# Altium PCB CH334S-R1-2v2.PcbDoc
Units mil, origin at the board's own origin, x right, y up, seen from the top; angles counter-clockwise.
Board outline 3110.24 x 866.14 mil, 2 copper layers (Top Layer, Bottom Layer); 18 components, 20 nets, 106 pads, 265 vias.
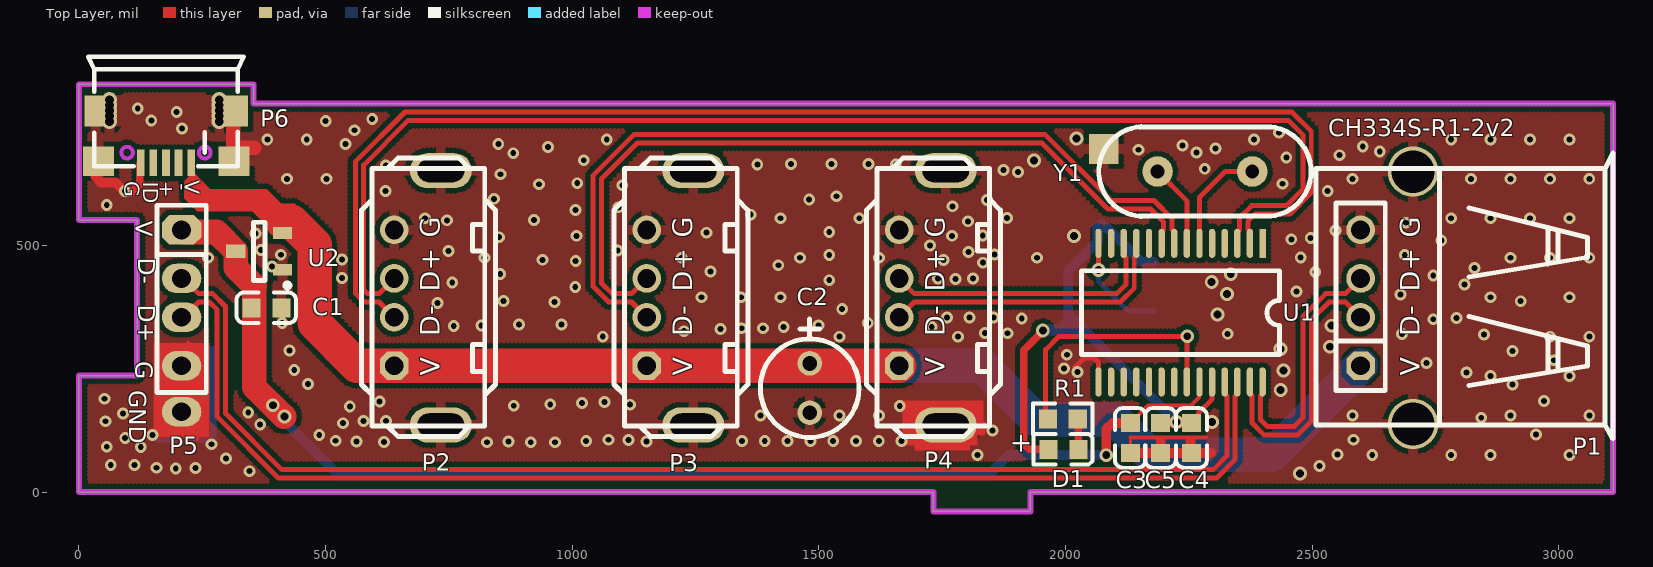
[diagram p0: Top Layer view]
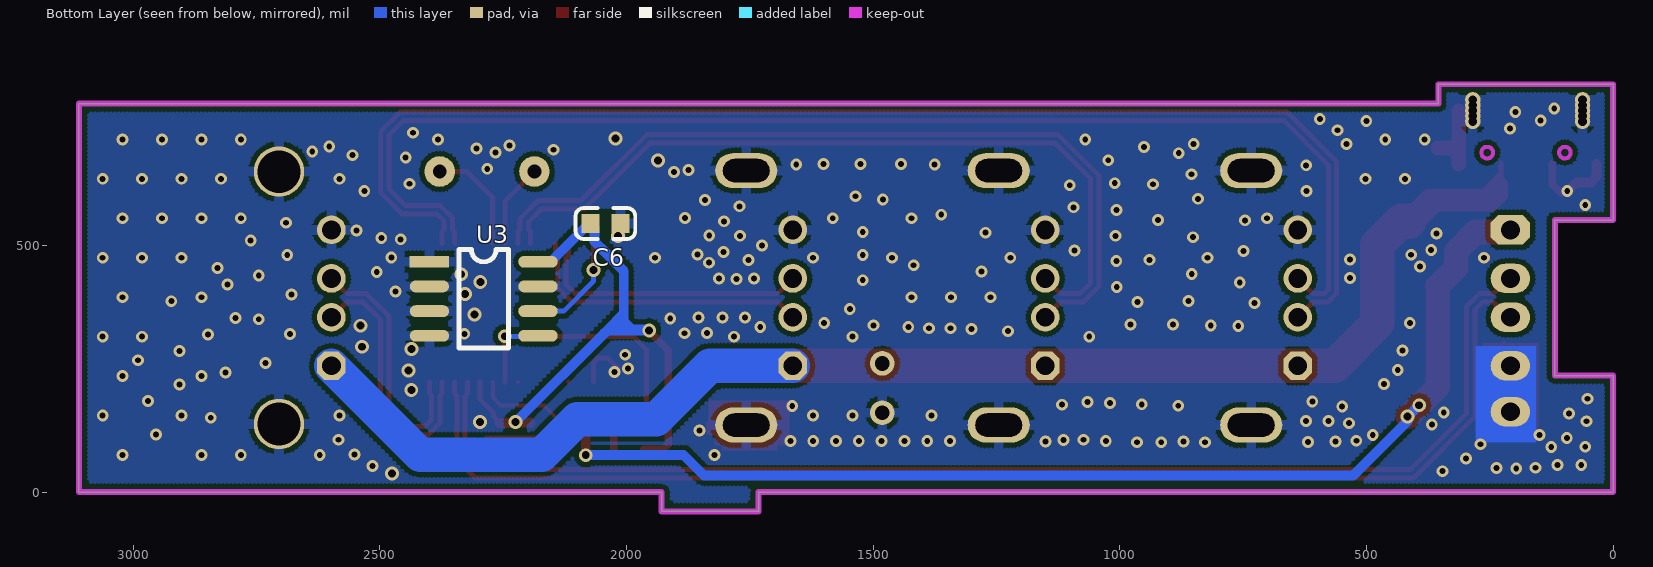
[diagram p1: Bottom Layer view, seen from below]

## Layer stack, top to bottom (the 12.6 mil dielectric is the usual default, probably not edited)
Top Solder: solder mask 0.4, Solder Resist, Dk 3.5
Top Layer: signal copper 1.4
Dielectric 1: dielectric 12.6, FR-4, Dk 4.8
Bottom Layer: signal copper 1.4
Bottom Solder: solder mask 0.4, Solder Resist, Dk 3.5

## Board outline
0,0 0,236.22 118.11,236.22 118.11,551.18 0,551.18 0,826.77 354.33,826.77 354.33,787.4 3110.24,787.4 3110.24,0 1929.13,0 1929.13,-39.37 1732.28,-39.37 1732.28,0

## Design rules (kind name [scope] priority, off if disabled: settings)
Clearance Clearance_1 [InPolygon] p1: gap=10 ignorepadtopadclearanceinfootprint=FALSE
Clearance [All] p2: gap=6 ignorepadtopadclearanceinfootprint=FALSE except(8: Arc-Via Track-Via SMDPad-Via THPad-Via Via-Via Via-Fill Via-Poly Via-Region Via-Hole)
ComponentClearance [All] p1 off: gap=10 collisioncheckmode=3 verticalgap=10 showdistances=FALSE
DiffPairsRouting [All] p1: maxlimit=10 minlimit=7 mostfreqgap=8 toplayer_minwidth=6 toplayer_maxwidth=15 toplayer_prefwidth=8 bottomlayer_minwidth=6 bottomlayer_maxwidth=15 bottomlayer_prefwidth=8 maxuncoupledlength=500
MinimumSolderMaskSliver [All] p1 off: minsoldermaskwidth=10
PolygonConnect PolygonConnect_1 [IsVia] p1: connectstyle=Direct reliefconductorwidth=10 reliefentries=4 polygonreliefangle="90 Angle" airgapwidth=10
PolygonConnect [All] p2: connectstyle=Relief reliefconductorwidth=20 reliefentries=4 polygonreliefangle="90 Angle" airgapwidth=10
RoutingVias [All] p1: holewidth=16 width=28 viastyle="Through Hole" minholewidth=12 minwidth=24 maxholewidth=28 maxwidth=50
SilkToSilkClearance [All] p1 off: silktosilkclearance=10
SilkToSolderMaskClearance [IsPad] p1 off: minsilkscreentomaskgap=10 clearancetoexposedcopper=TRUE
SolderMaskExpansion [All] p1: expansion=4 istentingtop=FALSE
Width [All] p1: maxlimit=100 minlimit=6 preferedwidth=10
25 further rules are at their usual default settings.

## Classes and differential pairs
differential pair UD: +UD_p -UD_n
differential pair UD4: +UD4_p -UD4_n
differential pair UD3: +UD3_p -UD3_n
differential pair UD2: +UD2_p -UD2_n
differential pair UD1: +UD1_p -UD1_n

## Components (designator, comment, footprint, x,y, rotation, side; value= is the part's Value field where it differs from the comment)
C1 "10uF" 0603_C 349.72,373.57 r0 top
C2 "220uF" CD0.1 1481.53,260.82 r270 top
C3 "1uF" 0603_C 2131.41,140.12 r270 top
C4 "0.1uF" 0603_C 2255.54,140.12 r270 top
C5 "10uF" 0603_C 2192.47,140.12 r270 top
C6 "NC(1uF)" 0603_C 2012.47,544.44 r0 bottom
D1 "LED" 0603+ 1965.61,86.66 r0 top
P1 "USB" USBAF#1 2598.25,255.91 r90 top
P2 "USB" USB2.0-A-F-TH_4P-V_13.7mm 639.21,255.91 r180 top
P3 "USB" USB2.0-A-F-TH_4P-V_13.7mm 1151.02,255.91 r180 top
P4 "USB" USB2.0-A-F-TH_4P-V_13.7mm 1662.83,255.91 r180 top
P5 "USB" USBAF#2 208.21,531.5 r270 top
P6 "Power Supply" USBMICROB-02-GXPX-A1T2 227.66,667.45 r180 top
R1 "1K" 0603_R 1994.55,148.31 r0 top
U1 "CH334S" SSOP28 2399.61,504.17 r180 top
U2 "CH213K" SOT-23-3 412.79,450.5 r90 top
U3 "NC(24C02)" SOIC-8_150mil 2399.58,466.78 r270 bottom
Y1 "12M" XT_AT49 2186.69,649.86 r270 top

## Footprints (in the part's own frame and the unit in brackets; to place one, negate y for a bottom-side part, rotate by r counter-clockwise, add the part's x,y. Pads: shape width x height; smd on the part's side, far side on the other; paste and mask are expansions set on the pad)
0603+ [mm]
  rect 0.93x0.98 smd: 1(0,0) 2(1.54,0)
  silkscreen extent -0.76,-0.79 2.27,0.79
0603_C [mm]
  rect 0.93x0.98 smd: 1(0,0) 2(1.54,0)
  silkscreen extent -0.76,-0.79 2.31,0.79
0603_R [mm]
  rect 0.93x0.98 smd: 1(-0.77,0) 2(0.77,0)
  silkscreen extent -1.53,-0.79 1.54,0.79
CD0.1 [mil]
  round 50 hole 30: 1(0,0) 2(100,0)
  silkscreen extent -90,-100 150,100
SOIC-8_150mil [mil]
  rect 24x80 smd: 1(0,0)
  oval 24x80 smd: 2(50,0) 3(100,0) 4(150,0) 5(150,220) 6(100,220) 7(50,220) 8(0,220)
  silkscreen extent -25,60 175,160
SOT-23-3 [mm] "SOT-23-3"
  rect 0.6x1 smd: 1(0,0) 2(1.9,0)
  rect 0.7x1 smd: 3(0.95,2.4)
  silkscreen extent -0.93,-0.38 2.45,1.49
SSOP28 [mil]
  rect 13x59.06 smd: 1(0,0)
  oval 13x59.06 smd: 2(25.59,0) 3(51.18,0) 4(76.77,0) 5(102.36,0) 6(127.95,0) 7(153.55,0) 8(179.14,0) 9(204.73,0) 10(230.32,0) 11(255.91,0) 12(281.5,0) 13(307.09,0) 14(332.68,0) 15(332.68,280.94) 16(307.09,280.94) 17(281.5,280.94) 18(255.91,280.94) 19(230.32,280.94) 20(204.73,280.94) 21(179.14,280.94) 22(153.55,280.94) 23(127.95,280.94) 24(102.36,280.94) 25(76.77,280.94) 26(51.18,280.94) 27(25.59,280.94) 28(0,280.94)
  silkscreen extent -34,55 367,225
USB2.0-A-F-TH_4P-V_13.7mm [mm]
  oval 3.2x1.8 hole 1.2 slot 2.4 at 0 deg: 0(-2.4,3.05) 0(-2.4,-10.05)
  oct 1.473x1.473 hole 0.965: 1(0,0)
  round 1.473 hole 0.965: 2(0,-2.5) 3(0,-4.5) 4(0,-7)
  silkscreen extent -5.21,-10.71 1.69,3.65
USBAF#1 [mm]
  round 2.6 hole 2.2: 0(-3,-2.7) 0(10,-2.7)
  oct 1.473x1.473 hole 0.965: 1(0,0)
  round 1.473 hole 0.965: 2(2.5,0) 3(4.5,0) 4(7,0)
  silkscreen extent -3.75,-12.99 10.95,2.29
USBAF#2 [mm]
  oct 1.524x2.032 hole 0.965: 1(0,0)
  oval 1.524x2.032 hole 0.965: 2(2.5,0) 3(4.5,0) 4(7,0)
  silkscreen extent -1.27,-1.27 8.38,1.27
USBMICROB-02-GXPX-A1T2 [mm]
  rect 1.6x1.5 smd: 0(-2.203,-0.083) 0(4.769,-0.083)
  rect 1.5x1.6 smd: 0(-2.167,-2.675)
  round 0.8 hole 0.45: 0(-1.442,-2.134) 0(-1.442,-3.243) 0(-1.442,-2.966) 0(-1.442,-2.689) 0(-1.442,-2.411) 0(4.208,-2.689) 0(4.208,-2.411) 0(4.208,-2.134) 0(4.208,-3.243) 0(4.208,-2.966)
  rect 1.1x1.6 smd: 0(4.933,-2.675)
  rect 0.4x1.35 smd mask+0.051: 1(0,0) 2(0.65,0) 3(1.3,0) 4(1.95,0) 5(2.6,0)
  Keep-Out Layer circle w0.203: c3.3,-0.525 r0.3
  Keep-Out Layer circle w0.203: c-0.7,-0.525 r0.3
  silkscreen extent -2.7,-5.46 5.3,0.17
XT_AT49 [mil]
  rect 60x60 smd: 0(-45.58,-109.21)
  round 62 hole 28: 1(0,0) 2(0,192.13)
  silkscreen extent -91,-119 91,311

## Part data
C1 C2 C3 C4 C5 C6: library part CAP, "Capacitor"
D1: "Typical INFRARED GaAs LED"
P1 P2 P3 P4 P5: "USB Port"
P6: library part MicroUSB, "MicroUSB Port"
R1: library part RES
U1: "4 ports High-Speed USB MTT Hub with over current detect & power control"
U2: "Ideal Diode 5V*1A"
U3: library part 24C01
Y1: library part XTAL, "Crystal Oscillator"

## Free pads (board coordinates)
  oval 80x60 hole 38: ""(208.21,162.81)

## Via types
v1: diameter 24, hole 12, Top Layer to Bottom Layer, tented both sides, 244 vias
v2: diameter 28, hole 16, Top Layer to Bottom Layer, tented both sides, 21 vias

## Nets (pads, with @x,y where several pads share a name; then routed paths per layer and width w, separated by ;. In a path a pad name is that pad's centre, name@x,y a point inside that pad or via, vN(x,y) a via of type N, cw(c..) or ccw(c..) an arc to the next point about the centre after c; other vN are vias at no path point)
3V3: C4.1 C5.1 C6.2 D1.1 U1.24 U3.8 | length 1306.8
  Top Layer w10: C4.1 2256.52,140.12 2269.83,153.42 2269.83,160.8 2297.24,188.22 U1.24
  Top Layer w15: v2@1955.31,326.94 1915.66,287.29 1915.66,97.02 1926.01,86.66 D1.1
  Top Layer w20: C5.1@2194.47,140.12 2195.41,141.06 2226.06,141.06 v2@2227,142 ; C4.1@2237.62,140.12 C4.1 ; C4.1@2256.52,140.12 C4.1@2257.54,140.12
  Bottom Layer w15: C6.2@2064.8,536.13 C6.2@2072.81,544.15
  Bottom Layer w20: 2046.1,320.9 2039.17,327.83 ; C6.2@2064.8,536.13 2064.8,507.72 2041.11,484.04 2005.6,448.52 2005.6,361.4 ; C6.2 2073.1,543.46 2081.41,535.15 2085.34,535.15 2150.81,469.67 2150.81,468.63 2152.66,466.78 U3.8 ; v2(2225,142) 2039.17,327.83 ; 2005.6,346.08 2017.36,334.31 2017.36,327.83 ; 2005.6,346.08 1988.88,329.36 1955.67,329.36 v2(1954.14,327.83) 2017.36,327.83 ; 2005.6,346.08 2005.6,361.4 ; 2005.6,361.4 2039.17,327.83 ; 2017.36,327.83 2039.17,327.83
5V: C1.1 C3.1 P5.1 U1.23 U2.3 | length 2567.6
  Top Layer w8: C3.1@2137.9,145.62 2167.61,175.34 2254.67,175.34 2270.69,191.36 2270.69,222.27 U1.23
  Top Layer w20: v2@2079.1,75.57 2079.75,75.57 2082.69,78.5 2082.69,127.54 2095.26,140.12 C3.1
  Top Layer w50: P5.1 212.43,527.28 278.91,527.28 U2.3 318.3,455.01 355.99,417.32 ; 355.63,417.23 355.63,212.8 415.22,153.21 v2(416.59,153.21)
  Bottom Layer w20: v2(393.17,176.02) 415.98,153.21 v2(416.59,153.21) 416.59,143.65 526.89,33.35 1843.13,33.35 1884.59,74.81 v2(2082.69,74.81)
GND: C1.2 C2.2 C3.2 C4.2 C5.2 C6.1 P1.0 P1.4 P2.0 P2.4 P3.0 P3.4 P4.0 P4.4 P5.4 P6.0 P6.5 pad. U1.15 U2.1 U3.1 U3.2 U3.3 U3.4 U3.7 Y1.0 | length 1674.6
  Top Layer w6: C3.2@2130.42,79.49 C3.2 2131.84,79.92 2131.84,110.91
  Top Layer w8: 220.81,208.41 220.81,302.53 ; 222,112.53 222,206.65 ; 225,112.53 225,206.65 ; 227.09,204.87 227.09,299 ; 230,111.08 230,205.21 ; 233,204.17 233,298.3 ; 234,111.08 234,205.21 ; 240,107.99 240,295.21 ; 1834.11,119.74 1834.11,140.29 ; 2131.84,110.91 2284.91,110.91
  Top Layer w10: v1@2018.16,251.58 2038.29,271.71 2057.73,271.71 2066.92,262.52 U1.15
  Top Layer w15: 104.84,605.5 123.71,624.36 P6.5@123.71,665.85
  Top Layer w20: P6.0@33.46,665 33.46,639.41 45.12,627.76 74.35,627.76 91.94,610.17 v1(93.02,610.17) ; C3.2@2143.41,79.49 C5.2 ; 2193.1,104.25 2193.1,80.12 C5.2 ; 2253.6,102.98 2253.6,81.43 C4.2@2255.33,79.69 ; C4.2@2255.68,80.03 C4.2@2255.33,79.69 ; 2294.68,79.49 C4.2 ; C5.2 C4.2 ; C4.2@2255.33,79.69 C4.2
  Top Layer w30: P6.0@312.99,665 P6.0@312.99,682.72 ; P6.0@312.99,772.76 P6.0@312.99,682.72 ; 354.76,697.24 327.52,697.24 P6.0@312.99,682.72
  other v1: 345.77,42.29 196.36,47.86 157.58,49.29 236.59,48.81 2514.7,52.91 64.67,55.04 112.56,54.56 298,68.06 1822,75 2622,75 2782,75 2862,75 3022,75 2551.51,75.81 125.49,91.43 56.53,91.91 269.09,96.97 618.87,101.5 827.57,100.98 916.07,100.98 965.42,100.98 563.05,102.8 870.97,102.68 1150.93,102.68 1344.12,103.19 1390.38,103.19 1436.63,103.19 1482.89,103.19 1529.14,103.19 1575.4,103.19 1621.65,103.19 1667.91,103.19 520.64,104.1 1028.39,103.53 1114.34,105.23 1073.49,106.08 2584.23,106.08 93.89,109.63 149.43,115.38 487.31,115.35 2953.66,116.98 1852.19,124.57 367.57,137.22 535.35,139.58 54.14,143.63 576.89,143.91 622.77,143.91 2842.89,150.73 1382,155 1542,155 1622,155 2582,155 2902,155 3062,155 89.58,159.43 343.43,161.36 549.2,173.34 1664.05,174.13 881.63,174.96 1117.55,177.16 955.63,177.89 1020.11,180.82 1065.53,182.28 609.78,183.72 2970.04,184.47 51.74,189.12 2906.47,218.22 464.25,219.13 2862,235 3022,235 2813.04,242.58 2024.13,243.72 436.59,247.6 1997.08,250.32 2732.05,261.79 2990.27,267.24 2002.74,278.31 2906.47,285.71 426.82,286.65 1062,315 1542,315 1782,315 2982,315 3062,315 2848.67,319.45 2328.89,320.81 2681.97,320.55 1837.22,322.36 1882.4,321.92 1226.76,326.1 1300.83,330.59 1343.48,332.09 1386.87,332.09 1428.77,334.33 1729.02,334.29 760.01,336.88 815.69,337.61 1499.1,338.08 891.89,339.81 978.34,339.81 412.17,342.93 1599.31,342.91 2745.54,350.41 1911.35,351.75 2792.74,353.2 1759.58,353.55 1805.52,353.88 1854.11,354.21 1547.41,370.82 727.04,383.04 964.42,385.23 861.12,387.43 2922.84,386.94 1262,395 1342,395 1422,395 2862,395 3022,395 2679.08,400.49 2468.51,406.66 1006.25,415.39 2809.11,420.69 756.97,424.97 1521.18,429.51 1776.76,432.22 1741.73,433.21 1812.79,433.21 533.4,433.86 2745.54,439.02 854.15,442.08 2506.38,445.9 1280.14,447.3 2829.34,454.43 391.37,457.01 1417.86,459.82 1833.07,465.02 1007.16,468.13 1752.63,470.43 533.4,471.42 939.67,470.84 262,475 822,475 1222,475 1462,475 1622,475 1942,475 2902,475 2982,475 3062,475 2476.88,475.71 2687.75,480.44 409.38,481.16 1521.18,480.68 1856.49,481.8 1803.47,486.72 749.2,488.72 1092.03,489.51 368.82,491 1725.48,499.88 2761.91,510.3 2457.89,512.35 2497.15,515.15 851.82,516.71 1009,519.49 1769.94,519.47 1832.29,520.21 358.22,524.02 1272.17,525.84 1521.18,527.32 2547.29,530.47 2690.64,545.94 1802.57,548.85 746.09,550.91 922.56,551.69 702,555 1422,555 1582,555 1881.66,555.45 2782,555 2862,555 2942,555 3022,555 1362.09,562.26 1006.71,571.47 1093.71,577.24 1770.67,579.29 56.52,582.14 1840.91,592.02 1480.46,592.99 841.71,594.45 1535.62,599.64 621.84,610.24 2531.58,610.33 1101.53,621.94 932.67,623.99 2440.25,624.99 1010.25,626.12 422,635 502,635 2582,635 2822,635 2902,635 2982,635 3062,635 854.93,644.21 1903.91,649.01 1874.26,653 2282.34,655.33 622.24,662.42 1375.3,663.89 1655.97,663.89 1443.81,664.72 1525.54,664.72 1600.66,664.72 1023.41,672.66 2447.74,677.92 2555.52,682.93 880.58,686.96 2265.57,688.39 2637.09,690.68 2147.83,693.96 2304.1,696.36 951.33,699.4 2602.63,700.27 2237.57,702.58 540.34,705.78 850.26,705.62 382,715 462,715 1070.19,714.85 2382,715 2782,715 2862,715 2942,715 3022,715 2432.81,728.4 559.03,733.42 209.17,737.14 500.31,752.44 146.87,753.14 594.56,756.21 198.29,770.28 119.32,777.75
  other v2: 2475.22,37.75 2297.01,142.03 2436.31,206.67 2441.83,246.32 2435.98,289.88 2536.57,294.55 2539.46,337.29 2307.95,360.01 2327.43,401.5 2296.4,425.67 2335,441.54 2017.32,519.17 1936.01,672.29 2022.31,716.63
NetD1_2: D1.2 R1.2 | length 57.8
  Top Layer w15: D1.2 2025.56,87.35 2025.56,137.89 R1.2@2029.99,142.32
NetU1_6: U1.6 Y1.2 | length 222.1
  Top Layer w10: U1.6 2271.65,597.34 2324.18,649.86 Y1.2
NetU1_7: U1.7 Y1.1 | length 170.3
  Top Layer w10: Y1.1 2246.06,590.49 U1.7
RST: U1.13
SCL: U1.14 U3.6 | length 214.6
  Top Layer w10: v2(2066.88,449.94) 2066.92,449.99 U1.14
  Bottom Layer w10: v2(2066.88,449.94) 2066.88,427.44 2127.54,366.78 U3.6
SDA: R1.1 U1.22 U3.5 | length 593.7
  Top Layer w10: R1.1@1959.96,154.19 1959.96,288.84 1986.87,315.76 v2(2246.82,315.76) 2246.63,315.58 2246.63,223.8 U1.22
  Bottom Layer w10: U3.5 2181.21,315.15 2181.83,315.76 v2(2246.82,315.76)
UD1_n: P1.2 U1.27 | length 560
  Top Layer w10: U1.27 2374.02,199.39 2378.31,195.09 2378.31,139.89 2402.35,115.85 2471.05,115.85 2498.46,143.26 2498.46,349.12 2534.54,385.2 2567.38,385.2 P1.2
UD1_p: P1.3 U1.28 | length 531.8
  Top Layer w10: U1.28 2399.61,199.39 2395.31,195.09 2395.31,146.94 2409.39,132.85 2464.01,132.85 2481.46,150.3 2481.46,356.16 2527.5,402.2 2567.38,402.2 P1.3
UD2_n: P2.2 U1.2 | length 2685
  Top Layer w10: P2.2 608.34,385.2 578.03,385.2 560.37,402.86 560.37,669.77 660.99,770.4 2459.03,770.4 2498.27,731.16 2498.27,606.77 2455.08,563.58 2384.6,563.58 2369.72,548.7 2369.72,532.31 2374.02,528.01 U1.2
UD2_p: P2.3 U1.3 | length 2600.5
  Top Layer w10: P2.3 608.34,402.2 585.07,402.2 577.37,409.9 577.37,662.73 668.04,753.4 1855.31,753.4 1871.07,753.4 2451.99,753.4 2481.27,724.12 2481.27,613.81 2448.04,580.58 2377.56,580.58 2352.72,555.74 2352.72,532.31 2348.42,528.01 U1.3
UD3_n: P3.2 U1.8 | length 1690.2
  Top Layer w10: P3.2 1120.15,385.2 1073.88,385.2 1042.46,416.63 1042.46,642.09 1125.07,724.7 1959.08,724.7 2092.85,590.92 2179.42,590.92 2216.17,554.17 2216.17,532.31 2220.47,528.01 U1.8
UD3_p: P3.3 U1.9 | length 1605.7
  Top Layer w10: P3.3 1120.15,402.2 1080.92,402.2 1059.46,423.67 1059.46,635.05 1132.11,707.7 1952.04,707.7 2085.81,573.92 2172.38,573.92 2199.17,547.13 2199.17,532.31 2194.88,528.01 U1.9
UD4_n: P4.2 U1.11 | length 593.6
  Top Layer w10: P4.2 1693.7,385.2 2111.27,385.2 2139.4,413.34 2139.4,476.04 2143.7,480.33 U1.11
UD4_p: P4.3 U1.12 | length 565.5
  Top Layer w10: P4.3 1693.7,402.2 2104.22,402.2 2122.4,420.38 2122.4,476.04 2118.1,480.33 U1.12
UD_n: P5.2 U1.25 | length 2569.8
  Top Layer w10: P5.2 211.83,433.07 242.7,402.2 271.31,402.2 297.25,376.26 297.25,159.68 411.47,45.46 2299.59,45.46 2327.13,72.99 2327.13,195.09 2322.83,199.39 U1.25
UD_p: P5.3 U1.26 | length 2597.9
  Top Layer w10: P5.3 211.83,354.33 242.7,385.2 264.27,385.2 280.25,369.22 280.25,152.64 404.43,28.46 2306.64,28.46 2344.13,65.95 2344.13,195.09 2348.42,199.39 U1.26
VBUS: C2.1 P1.1 P2.1 P3.1 P4.1 P6.1 U2.2 | length 3154.2
  Top Layer w10: 247.13,591.38 252.13,591.38 ; 252.85,603.63 251.45,605.02 ; 252.85,608.63 252.85,605.02 ; 254.37,584.14 259.37,584.14 ; 267.21,605.02 262.21,605.02 ; 276.12,579.63 263.88,579.63 ; 219.15,602.21 219.15,629.22 226.76,636.83 226.76,666.54 P6.1 P6.1@227.66,646.78 ; 219.15,602.21 219.15,597.21 236.73,579.63 241.73,579.63 ; 219.15,602.21 241.73,579.63 ; 227.66,615.85 227.66,619.83 ; 227.66,615.85 238.49,605.02 ; 227.66,615.85 227.66,604.47 252.5,579.63 ; 227.66,619.83 242.47,605.02 ; 227.66,619.83 227.66,628.81 ; 227.66,628.81 251.45,605.02 ; 227.66,628.81 P6.1@227.66,646.78 ; P6.1@227.66,646.78 234.14,640.3 ; 234.14,640.3 274.41,600.02 267.21,600.02 ; 234.14,640.3 234.14,633.09 262.21,605.02 ; 238.49,605.02 242.47,605.02 ; 238.49,605.02 252.13,591.38 ; 241.73,579.63 252.5,579.63 ; 242.47,605.02 251.45,605.02 ; 242.47,605.02 247.47,600.02 257.85,600.02 ; 251.45,605.02 252.85,605.02 ; 252.13,591.38 259.37,584.14 ; 252.13,591.38 266.49,591.38 257.85,600.02 ; 252.5,579.63 263.88,579.63 ; 252.85,605.02 262.21,605.02 ; 252.85,605.02 257.85,600.02 ; 257.85,600.02 267.21,600.02 ; 259.37,584.14 263.88,579.63 ; 262.21,605.02 267.21,600.02
  Top Layer w70: 413.54,547.71 431.57,547.71 477.8,501.47 477.8,341.91 563.81,255.91 P2.1 P3.1 P4.1
  Bottom Layer w70: P4.1 1831.73,255.91 1939.62,148.02 2099.63,148.02 2171.9,75.75 2418.1,75.75 P1.1
pads on no net: P6.2 P6.3 P6.4 U1.1 U1.4 U1.5 U1.10 U1.16 U1.17 U1.18 U1.19 U1.20 U1.21
copper on no net: | length 1.9
  Top Layer w8: 2117.23,224.1 2118.1,223.23 ; 2220.02,223.68 2220.47,223.23

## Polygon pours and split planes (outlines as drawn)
GND on Top Layer "GND" (hatched 90Degree grid 8 track 8, remove dead copper, pour order 0): 0,826.77 0,551.18 118.11,551.18 118.11,236.22 0,236.22 0,0 1732.28,0 1732.28,-39.37 1929.13,-39.37 1929.13,0 3110.24,0 3110.24,787.4 354.33,787.4 354.33,826.77
GND on Bottom Layer "GND" (hatched 90Degree grid 8 track 8, remove dead copper, pour order 1): 0,826.77 0,551.18 118.11,551.18 118.11,236.22 0,236.22 0,0 1732.28,0 1732.28,-39.37 1929.13,-39.37 1929.13,0 3110.24,0 3110.24,787.4 354.33,787.4 354.33,826.77

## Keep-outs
Keep-Out Layer:
  the board outline again, w12

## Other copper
Top Layer:
  rectangle net GND: 1694,84.44 1806,101.7
  rectangle net GND: 1668.7,94.34 1822.2,119.42
  rectangle net GND: 1669.7,115 1834.11,185.26
  rectangle net GND: 151.31,111.08 265.24,302.38
  region net VBUS: 213.99,626.45 213.99,595.67 240.1,569.56 351.68,569.56 398.95,522.29 439.9,522.29 451.44,533.83 451.44,571.48 437.98,584.95 410.19,584.95 380.78,614.35 265.93,614.36 253.41,626.87 240.24,626.87
Bottom Layer:
  rectangle net GND: 156.56,100.86 278.7,295.9

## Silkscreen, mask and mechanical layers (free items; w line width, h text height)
Top Overlay:
  lines w10: 255.22,688.12 255.22,729.37
  text "CH334S-R1-2v2" at 2532.39,721.18 h35
  text "GND" at 102.23,206.83 h35 r270
Mechanical 1:
  lines w10: 0,0 0,236.22 118.11,236.22 118.11,551.18 0,551.18 0,787.4 0,826.77 354.33,826.77 354.33,787.4 3110.24,787.4 3110.24,0 1929.13,0 1929.13,-39.37 1732.28,-39.37 1732.28,0 0,0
